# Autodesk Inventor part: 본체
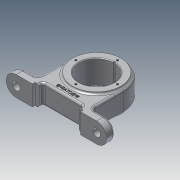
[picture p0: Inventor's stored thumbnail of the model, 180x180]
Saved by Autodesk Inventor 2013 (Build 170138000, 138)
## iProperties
Created: 2019-05
Part Number: 본체
Material: 알루미늄 6061
Document SubType Name: Modeling
Designer: user
Density: 2.71 g/cm^3
Mass: 457.703 g
Surface Area: 318.799 cm^2
Volume: 168.894 cm^3
Author: user
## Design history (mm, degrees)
sketch "스케치1"
  geometry: L1 (-40, 0)-(-40, -48); L2 (40, 0)-(40, -48); L3 (40, -48)-(-40, -48); A1 r 40 centre (0, 0) between (-40, 0) and (40, 0); 1 further point
  constraints: 6 end point, 2 point on circle, 2 tangent, 1 centre point, 1 coincident, 1 parallel, 1 perpendicular, 1 vertical
  dimensions: "d0" = 80 diameter of A1; "d2" = 48 distance of L1.start L1.end
extrude "돌출1" new body sketch "스케치1" stored distance "d3" = 30; taper "d4" = 0 deg
sketch "스케치2"
  geometry: C1 r 36 at (0, 0); C2 r 26 at (0, 0); A1 r 40 centre (0, 0) between (40, 0) and (-40, 0) reference
  constraints: 2 centre point, 2 coincident
  dimensions: "d5" = 72 diameter of C1; "d6" = 52 diameter of C2
extrude "돌출2" join sketch "스케치2" distance "d7" = 3; taper "d8" = 0 deg
sketch "스케치3"
  geometry: L1 (0, 0)-(0, 31); C1 r 36 at (0, 0) reference; 1 further point
  constraints: 2 end point, 1 coincident, 1 vertical
  dimensions: "d9" = 31 distance of L1.start L1.end
hole "구멍1" sketch "스케치3" at (0, 31) diameter "d10" = 3.242; stored, may be unused: countersink angle "d14" = 90 deg, drill point angle "d16" = 118 deg; dims "d11" = 6, "d12" = 4, "d13" = 2, "d15" = 8
sketch "스케치4"
  geometry: C1 r 26 at (0, 0) reference; C2 r 26 at (0, 0)
  constraints: 1 centre point, 1 coincident, 1 concentric
extrude "돌출3" cut sketch "스케치4" stored distance "d20" = 3; taper "d21" = 0 deg
node "작업 평면1"
sketch "스케치5"
  geometry: L1 (-60, 15)-(60, 15); L2 (60, 15)-(60, -15); L3 (60, -15)-(-60, -15); L4 (-60, -15)-(-60, 15); L5 (-60, 15)-(60, -15); L6 (60, 15)-(-60, -15); 3 further points
  constraints: 12 end point, 4 midpoint, 2 parallel, 2 vertical alignment, 1 horizontal, 1 perpendicular, 4 other
  dimensions: "d23" = 120 distance of L2.end L3.end; "d24" = 30 distance of L1.end L2.end
extrude "돌출4" join sketch "스케치5" distance "d25" = 12; taper "d26" = 0 deg
sketch "스케치6"
  geometry: L1 (60, -60)-(-60, -60) reference; L2 (-36, -60)-(-36, -56); L3 (-36, -56)-(-30, -56); L4 (-30, -56)-(-30, -50); L5 (-30, -50)-(30, -50); L6 (30, -50)-(30, -56); L7 (30, -56)-(36, -56); L8 (36, -56)-(36, -60); L9 (-36, -60)-(36, -60); C1 r 36 at (0, 0) reference; 1 further point
  constraints: 16 end point, 4 perpendicular, 3 parallel, 2 point on line, 1 collinear, 1 midpoint, 1 vertical alignment
  dimensions: "d27" = 72 distance between parallel lines of L8 L2; "d29" = 60 distance between parallel lines of L6 L4; "d30" = 4 distance between parallel lines of L1 L3; "d31" = 10 distance between parallel lines of L1 L5; "d32" = 4 distance between parallel lines of L1 L7; "d33" = 6 distance of L2.end L3.end
extrude "돌출5" cut sketch "스케치6" stored distance "d34" = 12; taper "d35" = 0 deg
sketch "스케치7"
  geometry: C1 r 9 at (-60, 0); A1 r 15 centre (-60, 0) between (-60, 15) and (-60, -15) reference; 1 further point
  constraints: 1 centre point, 1 coincident
  dimensions: "d36" = 18 diameter of C1
extrude "돌출6" join sketch "스케치7" distance "d37" = 3; taper "d38" = 0 deg
sketch "스케치8"
  geometry: C1 r 9 at (0, 0) reference; 2 further points
  constraints: 1 coincident
hole "구멍2" sketch "스케치8" at (0, 0) diameter "d39" = 11; stored, may be unused: countersink angle "d43" = 90 deg, drill point angle "d45" = 118 deg; dims "d40" = 6, "d41" = 4, "d42" = 2, "d44" = 8
sketch "스케치9"
  geometry: L1 (-30, -50)-(30, -50) reference; 2 further points
  constraints: 1 midpoint, 1 vertical alignment, 1 other
  dimensions: "d46" = 7 distance from line of L1 point (0, -43)
feature "엠보싱1" sketch "스케치9" dims "d0" = 80, "d2" = 48, "d47" = 0.5, "d48" = 0
node "작업 평면2"
sketch "스케치10"
  geometry: 2 further points
  constraints: 1 coincident
hole "구멍3" sketch "스케치10" at (0, 0) diameter "d50" = 4.917; stored, may be unused: countersink angle "d54" = 82 deg, drill point angle "d56" = 118 deg; dims "d51" = 8, "d52" = 7, "d53" = 1, "d55" = 10
sketch "스케치11"
  geometry: C1 r 1.621 at (0, 31) reference; C2 r 1.5 at (0, 26); 1 further point
  constraints: 2 vertical alignment, 1 centre point, 1 other
  dimensions: "d57" = 3 diameter of C2
extrude "돌출7" cut sketch "스케치11" stored distance "d58" = 3; taper "d59" = 0 deg
sketch "스케치12"
  geometry: 2 further points
  constraints: 1 coincident
hole "구멍4" sketch "스케치12" at (0, 0) diameter "d60" = 2; stored, may be unused: countersink angle "d64" = 82 deg, drill point angle "d66" = 118 deg; dims "d61" = 8, "d62" = 7, "d63" = 1, "d65" = 10
fillet "모깎기1" dims "d67" = 3
fillet "모깎기2" dims "d68" = 3
fillet "모깎기3" dims "d69" = 6
fillet "모깎기4" dims "d70" = 3
chamfer "모따기1" distance "d71" = 1; stored, may be unused: second distance "d72" = 2, angle "d73" = 45 deg
fillet "모깎기5" dims "d74" = 3
fillet "모깎기6" dims "d75" = 3
node "솔리드1"
pattern_circular "원형 패턴1" dims angle "d18" = 360 deg
mirror "대칭1"
mirror "대칭2"
mirror "대칭3"
